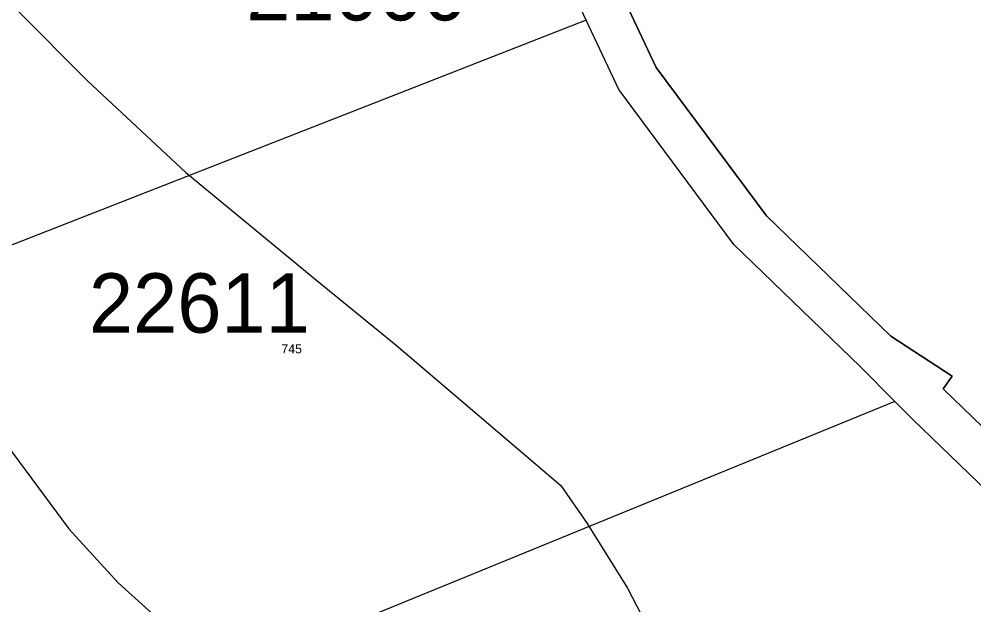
# Model space of a CAD drawing. Extents: x -725765 to -723182, y -1052705 to -1049154.
# Drawn here: x -723929.1 to -723752.1, y -1051204.1 to -1051095.6 of the extents above; entities that cross this region are included whole.
import ezdxf

# ---------------------------------------------------------------- set-up
doc = ezdxf.new("R2010")
doc.units = 0
for name, color, linetype in [('Vrstva 1', 7, 'Continuous'), ('Vrstva 13', 7, 'Continuous'), ('Vrstva 18', 7, 'Continuous'), ('Vrstva 52', 7, 'Continuous'), ('Vrstva 53', 7, 'Continuous')]:
    doc.layers.add(name, color=color, linetype=linetype)

msp = doc.modelspace()

# ---------------------------------------------------------------- linework, layer by layer
at = {"layer": 'Vrstva 1'}
for points in [[(-723823.99, -1051095.79), (-723892.14, -1050951.32)], [(-723823.99, -1051095.79), (-723987.97, -1051159.94)], [(-723817.93, -1051108.66), (-723823.99, -1051095.79)], [(-723796.62, -1051137.33), (-723817.93, -1051108.66)], [(-723773.17, -1051160), (-723796.62, -1051137.33)], [(-723766.76, -1051166.44), (-723773.17, -1051160)], [(-723766.76, -1051166.44), (-723899.8, -1051220.8)], [(-723763.47, -1051169.75), (-723766.76, -1051166.44)], [(-723746.11, -1051186.52), (-723763.47, -1051169.75)]]:
    msp.add_lwpolyline(points, dxfattribs=at)
at = {"layer": 'Vrstva 13'}
for points in [[(-723811.03, -1051104.53), (-723892.35, -1050932.12)], [(-723790.59, -1051132.03), (-723811.03, -1051104.53)], [(-723767.55, -1051154.3), (-723790.59, -1051132.03)], [(-723756.17, -1051161.72), (-723767.55, -1051154.3)], [(-723757.85, -1051164.05), (-723756.17, -1051161.72)], [(-723739.66, -1051181.63), (-723757.85, -1051164.05)]]:
    msp.add_lwpolyline(points, dxfattribs=at)
at = {"layer": 'Vrstva 52'}
for points in [[(-723906.46, -1050907.92), (-723892.35, -1050932.12), (-723811.03, -1051104.53), (-723790.59, -1051132.03), (-723767.55, -1051154.3), (-723756.17, -1051161.72), (-723757.85, -1051164.05), (-723739.66, -1051181.63), (-723720.66, -1051216.95), (-723672.97, -1051320.32), (-723623.01, -1051375.5)], [(-723955.19, -1051056), (-723954.69, -1051058), (-723942.13, -1051078), (-723929.38, -1051094), (-723916.38, -1051107), (-723898.13, -1051124), (-723873.88, -1051144), (-723859.19, -1051156), (-723833.31, -1051178), (-723828.69, -1051182), (-723823.81, -1051189), (-723816.31, -1051201), (-723811.13, -1051211)], [(-723982.81, -1051089), (-723974.31, -1051100), (-723964.13, -1051110), (-723957.63, -1051118), (-723950.38, -1051133), (-723938.38, -1051160), (-723930.19, -1051176), (-723919.81, -1051190), (-723910.69, -1051200), (-723901.88, -1051208), (-723883.81, -1051222), (-723881.61, -1051224.12)]]:
    msp.add_lwpolyline(points, dxfattribs=at)

# ---------------------------------------------------------------- texts
at = {"layer": 'Vrstva 18'}
msp.add_text('745', height=1.7, dxfattribs=at).set_placement((-723880.45, -1051157.51))
at = {"layer": 'Vrstva 53'}
for s, p in [('21000', (-723886.97, -1051095.83)), ('22611', (-723916.11, -1051153.68))]:
    msp.add_text(s, height=11, dxfattribs=at).set_placement(p)

doc.saveas('drawing.dxf')
